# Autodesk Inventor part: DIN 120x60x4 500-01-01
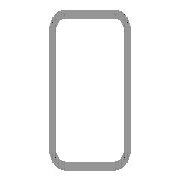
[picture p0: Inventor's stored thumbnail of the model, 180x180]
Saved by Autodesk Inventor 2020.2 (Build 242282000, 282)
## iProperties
Manager: www.cadconsulting.pl
Company: Fabian Stasiak CAD Consulting
IsCustomPart: 1
_CCFamilyMember: 190
_CCFamilyDisplayName: DIN 59410 (Prostokąt) - Rurki stalowe o przekroju prostokątnym formowane na gorąco — Standard DIN 59410 (Prostokąt) został wycofany i zastąpiony przez standard 
_FrameMemberDoc: Frame Member File
_Version: 15.0.0
_GetPNFromCC: 1
Created: 2015-02
Part Number: DIN 120x60x4 500-01-01
Material: Stal
Description: Rurki stalowe o przekroju prostokątnym formowane na gorąco
Document SubType Name: Modellieren
Standard: DIN
Designer: F.Stasiak
Standards Organization: DIN
Language: pl-PL
Size Designation: 120x60x4
Categories: <MemberInstance><Categories><Category DisplayName="Kształtowniki konstrukcyjne" InternalName="089c4875-fa83-4c05-b084-43b9cc11f5ed" Mnemonic="GRDR"><CategoryPar
Stock Number: 120x60x4
Density: 7.85 g/cm^3
Appearance: Płyta
G_L: 1800,000 mm
G_W: 60,000 mm
G_H: 120,000 mm
Author: F.Stasiak
Subject: Zbiór ćwiczeń. Autodesk Inventor 2020. Kurs podstawowy
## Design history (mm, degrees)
node "Płaszczyzna początkowa"
node "Płaszczyzna końcowa"
sketch "Szkic"
  geometry: L1 (-22, 60)-(22, 60); L2 (30, 52)-(30, -52); L3 (22, -60)-(-22, -60); L4 (-30, -52)-(-30, 52); L5 (-44.32, 0)-(44.32, 0) reference; L6 (0, -86.32)-(0, 86.32) reference; L7 (-22, 56)-(22, 56); L8 (26, 52)-(26, -52); L9 (22, -56)-(-22, -56); L10 (-26, -52)-(-26, 52); A1 r 8 centre (-22, 52) between (-22, 60) and (-30, 52); A2 r 8 centre (22, 52) between (30, 52) and (22, 60); A3 r 8 centre (22, -52) between (22, -60) and (30, -52); A4 r 8 centre (-22, -52) between (-30, -52) and (-22, -60); A5 r 4 centre (-22, 52) between (-22, 56) and (-26, 52); A6 r 4 centre (22, 52) between (26, 52) and (22, 56); A7 r 4 centre (22, -52) between (22, -56) and (26, -52); A8 r 4 centre (-22, -52) between (-26, -52) and (-22, -56); 3 further points
  constraints: 16 end point, 16 point on circle, 8 centre point, 8 tangent, 6 point on line, 4 parallel, 3 equal radius, 2 perpendicular, 1 horizontal, 7 other
  dimensions: "b" = 60 distance of point (-30, 60) point (30, 60); "ParH" = 120 distance of point (30, 60) point (30, -60); "msp_r" = 8 radius of A1 (= 2 x ParT); "d8" = 30 distance between parallel lines of L4 L6 (= 0.5 x b); "d9" = 60 distance between parallel lines of L5 L1 (= 0.5 x ParH); "d10" = 4 distance between parallel lines of L4 L10 (= ParT)
extrude "Bryła" new body sketch "Szkic" taper "d4" = 0 deg; stored distance "NLG" = 10
node "Driven Length"
  sketch "Sketch2"
    geometry: L1 (0, 0)-(10, 0) reference
    constraints: 2 end point, 1 horizontal
  workplane "Work Plane3"
  sketch "Sketch3"
    geometry: L1 (-2, 0)-(12, 0) reference; L2 (-2, 1800)-(12, 1800) reference
    dimensions: "d14" = 1800 distance between parallel lines of L1 L2 (derived)
body "Solid1"
other parameters: "ParT" = 4, "G_OFFSET_START" = 0 [user parameter; used in 1 equation term], "G_OFFSET_END" = 0 [user parameter; used in 1 equation term], "d11" = 0 (computed from G_OFFSET_START), "G_L" = 1800 (= d14) [user parameter], "d13" = 90 deg
